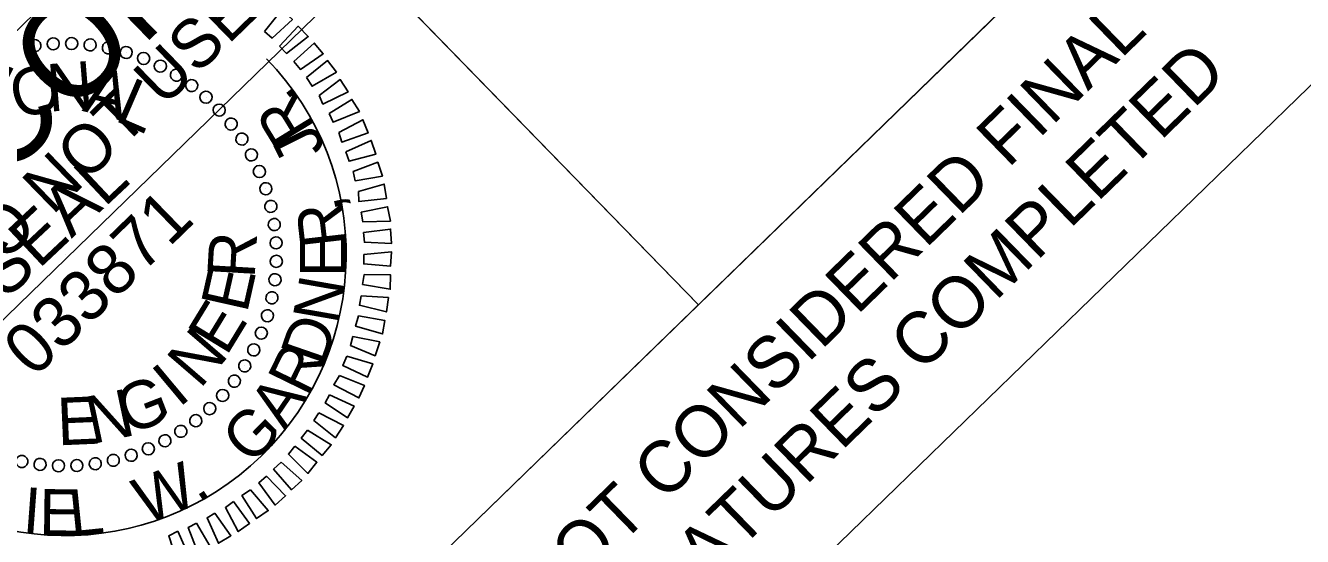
# Model space of a CAD drawing. Extents: x 2010880 to 2012866, y 442935 to 444909.
# Drawn here: x 2012051.6 to 2012203.1, y 444668.6 to 444729.3 of the extents above; entities that cross this region are included whole.
import ezdxf

# ---------------------------------------------------------------- set-up
doc = ezdxf.new("R2010")
doc.units = 0
for name, color, linetype in [('Scratch_Level_0', 7, 'Continuous'), ('Sheet Plan And Profile CELL', 7, 'Continuous'), ('Sheet Professional Seal CELL', 7, 'Continuous'), ('Sheet Profile Grid Minor CELL', 7, 'Continuous'), ('Sheet Sticker Exception Certification CELL', 7, 'Continuous'), ('Sheet Sticker Incomplete CELL', 7, 'Continuous')]:
    doc.layers.add(name, color=color, linetype=linetype)

msp = doc.modelspace()

# ---------------------------------------------------------------- linework, layer by layer
at = {"layer": 'Scratch_Level_0'}
msp.add_arc((2012056.26, 444702.1), 33.36, 224.1983, 44.1983, dxfattribs=at)
at = {"layer": 'Sheet Plan And Profile CELL'}
msp.add_line((2012052.98, 444776.8), (2012131.37, 444696.18), dxfattribs=at)
for points in [[(2012052.98, 444776.8), (2012124.67, 444846.52), (2012203.1, 444765.86), (2012131.41, 444696.15)], [(2011981.25, 444707.05), (2012052.98, 444776.8), (2012131.41, 444696.15), (2012059.68, 444626.4)]]:
    msp.add_lwpolyline(points, close=True, dxfattribs=at)
at = {"layer": 'Sheet Professional Seal CELL'}
for p, q in [((2012052.69, 444726.94), (2012052.69, 444726.94)), ((2012054.88, 444727.19), (2012054.88, 444727.19)), ((2012057.04, 444727.2), (2012057.04, 444727.2)), ((2012059.26, 444727.06), (2012059.26, 444727.06)), ((2012061.38, 444726.68), (2012061.38, 444726.68)), ((2012063.53, 444726.11), (2012063.53, 444726.11)), ((2012065.61, 444725.41), (2012065.61, 444725.41)), ((2012067.57, 444724.54), (2012067.57, 444724.54)), ((2012069.47, 444723.45), (2012069.47, 444723.45)), ((2012071.29, 444722.15), (2012071.29, 444722.15)), ((2012073, 444720.82), (2012073, 444720.82)), ((2012074.57, 444719.28), (2012074.57, 444719.28)), ((2012076, 444717.6), (2012076, 444717.6)), ((2012077.25, 444715.81), (2012077.25, 444715.81)), ((2012078.39, 444713.99), (2012078.39, 444713.99)), ((2012079.35, 444712), (2012079.35, 444712)), ((2012080.1, 444709.94), (2012080.1, 444709.94)), ((2012080.74, 444707.84), (2012080.74, 444707.84)), ((2012081.1, 444705.68), (2012081.1, 444705.68)), ((2012081.35, 444703.48), (2012081.35, 444703.48)), ((2012056.26, 444702.1), (2012056.26, 444702.1)), ((2012081.36, 444701.33), (2012081.36, 444701.33)), ((2012081.22, 444699.1), (2012081.22, 444699.1)), ((2012080.84, 444696.98), (2012080.84, 444696.98)), ((2012080.28, 444694.84), (2012080.28, 444694.84)), ((2012079.58, 444692.76), (2012079.58, 444692.76)), ((2012078.7, 444690.79), (2012078.7, 444690.79)), ((2012077.61, 444688.9), (2012077.61, 444688.9)), ((2012076.31, 444687.08), (2012076.31, 444687.08)), ((2012074.98, 444685.36), (2012074.98, 444685.36)), ((2012073.44, 444683.79), (2012073.44, 444683.79)), ((2012071.76, 444682.37), (2012071.76, 444682.37)), ((2012069.97, 444681.12), (2012069.97, 444681.12)), ((2012066.16, 444679.02), (2012066.16, 444679.02)), ((2012068.15, 444679.98), (2012068.15, 444679.98)), ((2012062, 444677.62), (2012062, 444677.62)), ((2012064.1, 444678.27), (2012064.1, 444678.27)), ((2012053.26, 444677.15), (2012053.26, 444677.15)), ((2012055.49, 444677.01), (2012055.49, 444677.01)), ((2012057.64, 444677.01), (2012057.64, 444677.01)), ((2012059.84, 444677.27), (2012059.84, 444677.27))]:
    msp.add_line(p, q, dxfattribs=at)
for points in [[(2012079.94, 444728.61), (2012081.99, 444731.16), (2012083.24, 444730.01), (2012080.84, 444727.82)], [(2012081.71, 444726.85), (2012083.94, 444729.22), (2012085.12, 444728), (2012082.55, 444725.99)], [(2012083.42, 444725.02), (2012085.82, 444727.22), (2012086.9, 444725.96), (2012084.19, 444724.09)], [(2012084.92, 444723.13), (2012087.42, 444725.14), (2012088.46, 444723.79), (2012085.57, 444722.09)], [(2012086.41, 444721.02), (2012088.91, 444722.9), (2012089.84, 444721.43), (2012086.85, 444719.99)], [(2012087.61, 444718.85), (2012090.29, 444720.54), (2012091.19, 444719.12), (2012088.06, 444717.82)], [(2012088.75, 444716.6), (2012091.6, 444718.12), (2012092.21, 444716.56), (2012089.09, 444715.47)], [(2012089.57, 444714.33), (2012092.59, 444715.67), (2012093.13, 444714.03), (2012089.97, 444713.19)], [(2012090.45, 444711.98), (2012093.37, 444713.07), (2012093.91, 444711.44), (2012090.68, 444710.88)], [(2012091.09, 444709.61), (2012094.14, 444710.48), (2012094.4, 444708.78), (2012091.14, 444708.4)], [(2012091.41, 444707.13), (2012094.53, 444707.79), (2012094.86, 444706.09), (2012091.61, 444705.99)], [(2012091.66, 444704.72), (2012094.88, 444705.13), (2012095, 444703.43), (2012091.78, 444703.58)], [(2012091.73, 444702.14), (2012094.99, 444702.44), (2012094.89, 444700.75), (2012091.71, 444701)], [(2012091.77, 444699.73), (2012094.88, 444699.69), (2012094.85, 444697.99), (2012091.57, 444698.57)], [(2012091.41, 444697.23), (2012094.63, 444697), (2012094.39, 444695.31), (2012091.18, 444696.1)], [(2012091.1, 444694.83), (2012094.2, 444694.29), (2012093.93, 444692.7), (2012090.73, 444693.63)], [(2012090.39, 444692.4), (2012093.6, 444691.75), (2012093.05, 444690.1), (2012090.13, 444691.3)], [(2012089.69, 444690.04), (2012092.78, 444689.14), (2012092.16, 444687.56), (2012089.21, 444688.95)], [(2012088.84, 444687.75), (2012091.79, 444686.58), (2012091.14, 444685.1), (2012088.15, 444686.66)], [(2012087.64, 444685.47), (2012090.56, 444684.12), (2012089.76, 444682.72), (2012087.13, 444684.49)], [(2012086.37, 444683.33), (2012089.32, 444681.8), (2012088.35, 444680.37), (2012085.8, 444682.42)], [(2012085.04, 444681.26), (2012087.84, 444679.53), (2012086.76, 444678.27), (2012084.28, 444680.32)], [(2012083.52, 444679.37), (2012086.15, 444677.46), (2012085.07, 444676.13), (2012082.77, 444678.43)], [(2012081.91, 444677.45), (2012084.35, 444675.3), (2012083.13, 444674.18), (2012081.01, 444676.65)], [(2012080.15, 444675.81), (2012082.42, 444673.48), (2012081.2, 444672.37), (2012079.26, 444675.01)], [(2012078.25, 444674.18), (2012080.38, 444671.71), (2012078.98, 444670.77), (2012077.25, 444673.49)], [(2012074.04, 444671.41), (2012075.95, 444668.73), (2012074.45, 444667.83), (2012073.12, 444670.86)], [(2012076.26, 444672.79), (2012078.16, 444670.18), (2012076.81, 444669.21), (2012075.29, 444672.06)], [(2012071.87, 444670.2), (2012073.49, 444667.46), (2012072.03, 444666.73), (2012070.87, 444669.72)], [(2012069.63, 444669.28), (2012071, 444666.22), (2012069.58, 444665.67), (2012068.56, 444668.73)]]:
    msp.add_lwpolyline(points, close=True, dxfattribs=at)
for centre, major_axis in [((2012052.69, 444726.93), (-0.103, 0.713)), ((2012054.86, 444727.14), (-0.04, 0.719)), ((2012057.05, 444727.17), (0.023, 0.72)), ((2012059.23, 444727.01), (0.085, 0.715)), ((2012061.39, 444726.65), (0.147, 0.705)), ((2012063.51, 444726.11), (0.208, 0.689)), ((2012065.58, 444725.39), (0.267, 0.669)), ((2012067.57, 444724.49), (0.325, 0.643)), ((2012069.48, 444723.42), (0.379, 0.612)), ((2012071.29, 444722.18), (0.431, 0.577)), ((2012072.98, 444720.8), (0.48, 0.537)), ((2012074.55, 444719.27), (0.525, 0.493)), ((2012075.97, 444717.61), (0.566, 0.445)), ((2012077.25, 444715.83), (0.602, 0.394)), ((2012078.37, 444713.95), (0.635, 0.34)), ((2012079.32, 444711.98), (0.662, 0.284)), ((2012080.09, 444709.93), (0.684, 0.225)), ((2012080.68, 444707.83), (0.701, 0.164)), ((2012081.09, 444705.68), (0.713, 0.103)), ((2012081.3, 444703.5), (0.719, 0.04)), ((2012081.33, 444701.31), (0.72, -0.023)), ((2012081.17, 444699.13), (0.715, -0.085)), ((2012080.81, 444696.97), (0.705, -0.147)), ((2012080.27, 444694.85), (0.689, -0.208)), ((2012079.55, 444692.79), (0.669, -0.267)), ((2012078.65, 444690.79), (0.643, -0.325)), ((2012077.58, 444688.89), (0.612, -0.379)), ((2012076.35, 444687.08), (0.577, -0.431)), ((2012074.96, 444685.38), (0.537, -0.48)), ((2012073.43, 444683.82), (0.493, -0.525)), ((2012071.77, 444682.39), (0.445, -0.566)), ((2012068.11, 444680), (0.34, -0.635)), ((2012070, 444681.12), (0.394, -0.602)), ((2012064.1, 444678.28), (0.225, -0.684)), ((2012066.14, 444679.05), (0.284, -0.662)), ((2012051.13, 444677.55), (-0.147, -0.705)), ((2012053.29, 444677.2), (-0.085, -0.715)), ((2012055.47, 444677.03), (-0.023, -0.72)), ((2012057.66, 444677.06), (0.04, -0.719)), ((2012059.84, 444677.28), (0.103, -0.713)), ((2012061.99, 444677.68), (0.164, -0.701))]:
    msp.add_ellipse(centre, major_axis=major_axis, ratio=0.999708, dxfattribs=at)
at = {"layer": 'Sheet Sticker Exception Certification CELL'}
for p, q in [((2012059.67, 444626.41), (2012203.09, 444765.87)), ((2012225.39, 444742.95), (2012081.96, 444603.48))]:
    msp.add_line(p, q, dxfattribs=at)
at = {"layer": 'Sheet Sticker Incomplete CELL'}
msp.add_lwpolyline([(2012039.5, 444685.24), (2012023.12, 444702.08), (2012128.51, 444804.56), (2012144.89, 444787.72)], close=True, dxfattribs=at)

# ---------------------------------------------------------------- texts
at = {"layer": 'Sheet Professional Seal CELL'}
for s, height, rotation, p in [('O', 5.64, 14.0317, (2012050.55, 444718.16)), ('N', 5.64, 4.6749, (2012054.34, 444719.07)), ('A', 5.64, 345.9585, (2012058.2, 444719.19)), ('L', 5.64, 336.5991, (2012062, 444718.07)), ('SEAL', 5.998, 43.1983, (2012049.22, 444696.65)), ('R', 5.64, 86.6797, (2012078.75, 444699.21)), ('E', 5.64, 77.3223, (2012077.84, 444695.05)), ('E', 5.64, 58.61, (2012075.4, 444689.95)), ('N', 5.64, 49.2546, (2012072.27, 444686.07)), ('I', 5.64, 39.8995, (2012069.76, 444683.84)), ('G', 5.64, 21.1885, (2012063.74, 444680.64)), ('E', 5.64, 2.4751, (2012055.42, 444679.45)), ('N', 5.64, 11.8322, (2012059.45, 444679.6))]:
    msp.add_text(s, height=height, rotation=rotation, dxfattribs=at).set_placement(p)
at = {"layer": 'Sheet Profile Grid Minor CELL'}
for s, height, rotation, p in [('R', 5.5, 121.5523, (2012086.09, 444717.29)), ('.', 5.5, 128.4788, (2012084.04, 444720.78)), ('J', 5.5, 116.6838, (2012087.27, 444714.71)), ('033871', 5.998, 44.1983, (2012052.6, 444687.37)), ('R', 5.5, 96.577, (2012089.71, 444703.28)), (',', 5.5, 103.5035, (2012089.33, 444707.3)), ('E', 5.5, 89.9941, (2012089.63, 444699.44)), ('N', 5.5, 80.0623, (2012088.67, 444693.72)), ('D', 5.5, 70.9177, (2012086.92, 444688.68)), ('R', 5.5, 63.9913, (2012085.08, 444685.08)), ('A', 5.5, 55.8055, (2012082.36, 444681.15)), ('G', 5.5, 45.8738, (2012078.36, 444676.96)), ('W', 5.5, 21.0874, (2012065.78, 444670.01)), ('I', 5.5, 355.7286, (2012051.12, 444669.03)), ('E', 5.5, 359.2491, (2012053.16, 444668.78)), ('L', 5.5, 5.8321, (2012057, 444668.64)), ('.', 5.5, 32.6935, (2012072.04, 444672.59))]:
    msp.add_text(s, height=height, rotation=rotation, dxfattribs=at).set_placement(p)
at = {"layer": 'Sheet Sticker Exception Certification CELL'}
for s, p in [('DOCUMENT NOT CONSIDERED FINAL', (2012077.82, 444624.42)), ('UNLESS ALL SIGNATURES COMPLETED', (2012080.86, 444613.07))]:
    msp.add_text(s, height=6.124, rotation=44.1983, dxfattribs=at).set_placement(p)
at = {"layer": 'Sheet Sticker Incomplete CELL'}
for s, height, p in [('INCOMPLETE PLANS', 11.52, (2012037.76, 444699.86)), ('DO NOT USE FOR R/W ACQUISITION', 5.76, (2012044.94, 444697.15))]:
    msp.add_text(s, height=height, rotation=44.1983, dxfattribs=at).set_placement(p)

doc.saveas('drawing.dxf')
